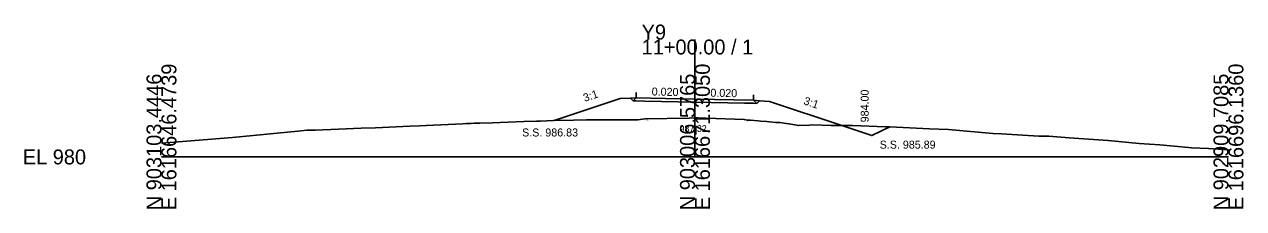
# Model space of a CAD drawing. Extents: x -26 to 1403, y -10 to 3021.
# Drawn here: x -25.7 to 202.8, y 990.3 to 1024.8 of the extents above; entities that cross this region are included whole.
import ezdxf

# ---------------------------------------------------------------- set-up
doc = ezdxf.new("R2010")
doc.units = 0
for name, color, linetype in [('Exist Cross Section Cell', 7, 'Continuous'), ('Exist XS Center Line Elevation Label', 7, 'Continuous'), ('Exist XS Ground Line', 7, 'Continuous'), ('Prop XS Dump Level', 7, 'Continuous'), ('Prop XS Earthwork Shape', 7, 'Continuous'), ('Prop XS EOT Tick Mark', 7, 'Continuous'), ('Prop XS Finish Grade', 7, 'Continuous'), ('Prop XS Finish Grade Earthwork', 7, 'Continuous'), ('Prop XS Finish Grade Pavement', 7, 'Continuous'), ('Prop XS Pvmt Edge Slope', 7, 'Continuous'), ('Prop XS SE Text', 7, 'Continuous'), ('Prop XS Side Slope Text', 7, 'Continuous'), ('Prop XS SS Elevation Text', 7, 'Continuous'), ('Prop XS Subgrade Earthwork', 7, 'Continuous')]:
    doc.layers.add(name, color=color, linetype=linetype)

msp = doc.modelspace()

# ---------------------------------------------------------------- linework, layer by layer
at = {"layer": 'Exist Cross Section Cell'}
for p, q in [((100, 1000), (100, 1022)), ((0, 1000), (100, 1000)), ((100, 1000), (200, 1000))]:
    msp.add_line(p, q, dxfattribs=at)
at = {"layer": 'Exist XS Ground Line'}
for p, q in [((40.11, 1005.48), (46.58, 1005.77)), ((46.58, 1005.77), (48.37, 1005.81)), ((48.37, 1005.81), (49.61, 1005.89)), ((49.61, 1005.89), (56.52, 1006.2)), ((56.52, 1006.2), (57.16, 1006.24)), ((57.16, 1006.24), (58.04, 1006.29)), ((58.04, 1006.29), (58.59, 1006.32)), ((58.59, 1006.32), (59.68, 1006.35)), ((59.68, 1006.35), (62.03, 1006.41)), ((62.03, 1006.41), (67.93, 1006.66)), ((67.93, 1006.66), (70.27, 1006.72)), ((70.27, 1006.72), (71.07, 1006.73)), ((71.07, 1006.73), (73.43, 1006.83)), ((73.43, 1006.83), (77.21, 1006.89)), ((77.21, 1006.89), (79.65, 1006.92)), ((79.65, 1006.92), (82.56, 1006.96)), ((82.56, 1006.96), (84.78, 1006.96)), ((84.78, 1006.96), (86.89, 1006.95)), ((86.89, 1006.95), (89.29, 1006.97)), ((89.29, 1006.97), (90.62, 1007.14)), ((90.62, 1007.14), (98.9, 1007.29)), ((98.9, 1007.29), (100, 1007.32)), ((100, 1007.32), (100.61, 1007.33)), ((100.61, 1007.33), (102.13, 1007.28)), ((102.13, 1007.28), (109.29, 1007.01)), ((109.29, 1007.01), (109.83, 1006.9)), ((109.83, 1006.9), (110.44, 1006.88)), ((110.44, 1006.88), (111.84, 1006.74)), ((111.84, 1006.74), (112.3, 1006.68)), ((112.3, 1006.68), (113.45, 1006.63)), ((113.45, 1006.63), (113.98, 1006.57)), ((113.98, 1006.57), (115.17, 1006.48)), ((115.17, 1006.48), (115.91, 1006.42)), ((115.91, 1006.42), (117.61, 1006.22)), ((117.61, 1006.22), (119.44, 1005.86)), ((119.44, 1005.86), (121.42, 1005.97)), ((121.42, 1005.97), (122.07, 1006)), ((122.07, 1006), (125.55, 1005.89)), ((125.55, 1005.89), (128.19, 1005.89)), ((128.19, 1005.89), (129.54, 1005.87)), ((129.54, 1005.87), (135.74, 1005.66)), ((135.74, 1005.66), (136.53, 1005.66)), ((136.53, 1005.66), (143.98, 1005.27)), ((0, 1002.6), (13.3, 1003.66)), ((13.3, 1003.66), (25.55, 1004.82)), ((25.55, 1004.82), (27.23, 1004.99)), ((27.23, 1004.99), (28.84, 1005.04)), ((28.84, 1005.04), (33.2, 1005.18)), ((33.2, 1005.18), (37.45, 1005.37)), ((37.45, 1005.37), (40.11, 1005.48)), ((143.98, 1005.27), (147.5, 1005.11)), ((147.5, 1005.11), (155.81, 1004.39)), ((155.81, 1004.39), (157.44, 1004.3)), ((157.44, 1004.3), (164.47, 1003.89)), ((164.47, 1003.89), (166.35, 1003.86)), ((166.35, 1003.86), (170.12, 1003.6)), ((170.12, 1003.6), (177.42, 1003.09)), ((177.42, 1003.09), (183.28, 1002.53)), ((183.28, 1002.53), (187.14, 1002.25)), ((187.14, 1002.25), (192.53, 1001.76)), ((192.53, 1001.76), (193.09, 1001.73)), ((193.09, 1001.73), (196.28, 1001.56)), ((196.28, 1001.56), (200, 1001.32))]:
    msp.add_line(p, q, dxfattribs=at)
at = {"layer": 'Prop XS Dump Level'}
for p, q in [((89, 1011.07), (100, 1010.85)), ((100, 1010.85), (111, 1010.63))]:
    msp.add_line(p, q, dxfattribs=at)
at = {"layer": 'Prop XS Earthwork Shape'}
for points in [[(109.83, 1006.9), (110.44, 1006.88), (111.84, 1006.74), (112.3, 1006.68), (113.45, 1006.63), (113.98, 1006.57), (115.17, 1006.48), (115.91, 1006.42), (117.61, 1006.22), (119.44, 1005.86), (121.42, 1005.97), (122.07, 1006), (125.55, 1005.89), (127.5, 1005.89), (114, 1010.39), (112.1, 1010.54), (111.6, 1010.04), (111, 1010.05), (109.29, 1010.08), (90.62, 1010.46), (89, 1010.49), (88.43, 1010.5), (87.9, 1011.03), (86, 1010.95), (73.64, 1006.83), (77.21, 1006.89), (79.65, 1006.92), (82.56, 1006.96), (84.78, 1006.96), (86.89, 1006.95), (89.29, 1006.97), (90.62, 1007.14), (98.9, 1007.29), (100, 1007.32), (100.61, 1007.33), (102.13, 1007.28), (109.29, 1007.01)], [(127.5, 1005.89), (128.19, 1005.89), (129.54, 1005.87), (135.74, 1005.66), (136.5, 1005.66), (133.17, 1004)]]:
    msp.add_lwpolyline(points, close=True, dxfattribs=at)
at = {"layer": 'Prop XS EOT Tick Mark'}
for p, q in [((89, 1011.07), (89, 1012.07)), ((111, 1010.63), (111, 1011.63))]:
    msp.add_line(p, q, dxfattribs=at)
at = {"layer": 'Prop XS Finish Grade'}
for p, q in [((89, 1011.07), (87.9, 1011.03)), ((111, 1010.63), (112.1, 1010.54))]:
    msp.add_line(p, q, dxfattribs=at)
at = {"layer": 'Prop XS Finish Grade Earthwork'}
for p, q in [((86, 1010.95), (73.64, 1006.83)), ((87.9, 1011.03), (86, 1010.95)), ((112.1, 1010.54), (114, 1010.39)), ((114, 1010.39), (127.5, 1005.89)), ((133.17, 1004), (127.5, 1005.89)), ((133.17, 1004), (136.5, 1005.66))]:
    msp.add_line(p, q, dxfattribs=at)
at = {"layer": 'Prop XS Finish Grade Pavement'}
for p, q in [((89, 1011.07), (100, 1010.85)), ((100, 1010.85), (111, 1010.63))]:
    msp.add_line(p, q, dxfattribs=at)
at = {"layer": 'Prop XS Pvmt Edge Slope'}
for p, q in [((89, 1011.07), (88.43, 1010.5)), ((111, 1010.63), (111.6, 1010.04))]:
    msp.add_line(p, q, dxfattribs=at)
at = {"layer": 'Prop XS Subgrade Earthwork'}
for p, q in [((88.43, 1010.5), (87.9, 1011.03)), ((89, 1010.49), (88.43, 1010.5)), ((90.62, 1010.46), (89, 1010.49)), ((90.62, 1010.46), (109.29, 1010.08)), ((111.6, 1010.04), (112.1, 1010.54)), ((109.29, 1010.08), (111, 1010.05)), ((111, 1010.05), (111.6, 1010.04))]:
    msp.add_line(p, q, dxfattribs=at)

# ---------------------------------------------------------------- texts
at = {"layer": 'Exist Cross Section Cell'}
for s, p in [('Y9', (90, 1022)), ('11+00.00 / 1', (90, 1019.2)), ('EL 980', (-26, 998.6))]:
    msp.add_text(s, height=2.8, dxfattribs=at).set_placement(p)
for s, p in [('E 1616646.4739', (2.8, 990)), ('E 1616671.3050', (102.8, 990)), ('E 1616696.1360', (202.8, 990)), ('N 903103.4446', (0, 990)), ('N 903006.5765', (100, 990)), ('N 902909.7085', (200, 990))]:
    msp.add_text(s, height=2.8, rotation=90, dxfattribs=at).set_placement(p)
at = {"layer": 'Exist XS Center Line Elevation Label'}
msp.add_text('987.32', height=1.25, dxfattribs=at).set_placement((97.1, 1004.69))
at = {"layer": 'Prop XS Dump Level'}
for s, height, p in [('Case1', 0.04, (86, 1010.91)), ('Case1', 0.04, (114, 1010.35)), ('Eop', 0.3, (90.62, 1006.84)), ('Eop', 0.3, (109.29, 1006.71))]:
    msp.add_text(s, height=height, dxfattribs=at).set_placement(p)
at = {"layer": 'Prop XS SE Text'}
for p in [(91.88, 1011.51), (102.88, 1011.29)]:
    msp.add_text('0.020', height=1.5, rotation=358.8542, dxfattribs=at).set_placement(p)
at = {"layer": 'Prop XS Side Slope Text'}
for rotation, p in [(18.4349, (79.34, 1010.31)), (341.5651, (120.24, 1009.89))]:
    msp.add_text('3:1', height=1.5, rotation=rotation, dxfattribs=at).set_placement(p)
at = {"layer": 'Prop XS SS Elevation Text'}
msp.add_text('984.00', height=1.5, rotation=90, dxfattribs=at).set_placement((132.56, 1006.48))
for s, p in [('S.S. 986.83', (67.6, 1003.83)), ('S.S. 985.89', (134.62, 1001.55))]:
    msp.add_text(s, height=1.5, dxfattribs=at).set_placement(p)

doc.saveas('drawing.dxf')
